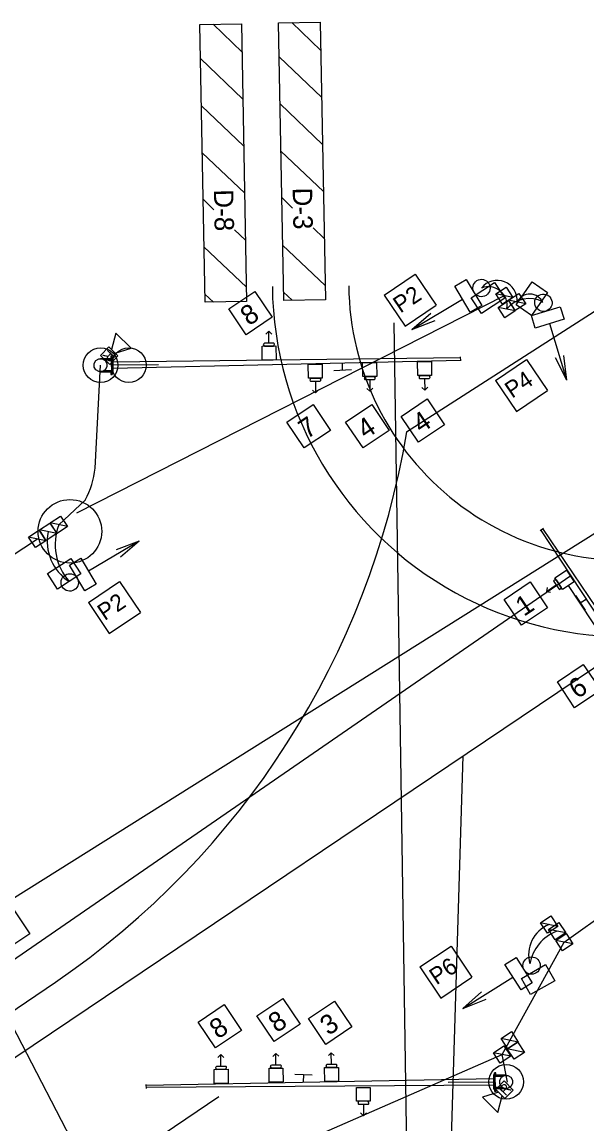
# Model space of a CAD drawing. Extents: x 509004 to 509991, y 882089 to 882397.
# Drawn here: x 509136.6 to 509218, y 882237.8 to 882396.5 of the extents above; entities that cross this region are included whole.
import ezdxf

# ---------------------------------------------------------------- set-up
doc = ezdxf.new("R2010")
doc.units = 0
for name, color, linetype in [('CLConst_dp', 7, 'Continuous'), ('ConstLines', 7, 'Continuous'), ('Default', 7, 'Continuous'), ('TextAlgnCardinalPnt', 7, 'Continuous'), ('TextAlgnCurveData', 7, 'Continuous'), ('TextAlgnStation100', 7, 'Continuous'), ('TextAlgnStation1000', 7, 'Continuous'), ('TextAlgnStation500', 7, 'Continuous'), ('TextAlgnTangent', 7, 'Continuous'), ('TextAlgnTicks1000', 7, 'Continuous'), ('TextAlgnTicks500', 7, 'Continuous'), ('TextAlgnTicks5000', 7, 'Continuous')]:
    doc.layers.add(name, color=color, linetype=linetype)

msp = doc.modelspace()

# ---------------------------------------------------------------- linework, layer by layer
at = {"layer": 'CLConst_dp'}
for p, q in [((509147.93, 882348.06), (509149.41, 882348.08)), ((509147.93, 882348.06), (509147.93, 882348)), ((509149.4, 882348.43), (509149.41, 882347.87)), ((509149.4, 882348.43), (509149.57, 882348.43)), ((509149.57, 882348.43), (509149.6, 882345.76)), ((509149.57, 882348.14), (509149.74, 882348.14)), ((509149.61, 882346.06), (509149.57, 882348.14)), ((509149.77, 882346.06), (509149.74, 882348.14)), ((509149.75, 882347.56), (509199.74, 882348.17)), ((509199.74, 882348.29), (509199.75, 882347.71)), ((509147.93, 882348), (509149.41, 882348.01)), ((509148.42, 882347.86), (509149.49, 882347.87)), ((509149.49, 882347.87), (509149.51, 882346.32)), ((509149.76, 882346.64), (509199.75, 882347.83)), ((509147.95, 882346.16), (509149.43, 882346.18)), ((509147.95, 882346.1), (509147.95, 882346.16)), ((509147.95, 882346.1), (509149.43, 882346.11)), ((509148.44, 882346.31), (509149.51, 882346.32)), ((509149.43, 882346.32), (509149.43, 882345.76)), ((509149.43, 882345.76), (509149.6, 882345.76)), ((509149.61, 882346.06), (509149.77, 882346.06)), ((509211.24, 882323.28), (509211.73, 882323.61)), ((509238.84, 882281.59), (509211.35, 882323.35)), ((509239.6, 882282.09), (509211.62, 882323.54)), ((509204.68, 882244.87), (509204.52, 882244.86)), ((509204.52, 882244.86), (509204.54, 882242.78)), ((509204.85, 882245.16), (509204.68, 882245.16)), ((509204.71, 882242.49), (509204.68, 882245.16)), ((509204.68, 882244.87), (509204.71, 882242.78)), ((509204.86, 882244.6), (509204.85, 882245.16)), ((509204.52, 882244.28), (509154.53, 882243.35)), ((509154.54, 882242.9), (509154.53, 882243.48)), ((509204.54, 882243.36), (509154.54, 882243.02)), ((509205.85, 882244.62), (509204.78, 882244.6)), ((509204.8, 882243.05), (509204.78, 882244.6)), ((509206.34, 882244.83), (509204.85, 882244.81)), ((509206.34, 882244.76), (509204.86, 882244.75)), ((509206.34, 882244.83), (509206.34, 882244.76)), ((509204.71, 882242.78), (509204.54, 882242.78)), ((509204.88, 882242.49), (509204.71, 882242.49)), ((509205.87, 882243.06), (509204.8, 882243.05)), ((509204.88, 882242.49), (509204.88, 882243.05)), ((509206.36, 882242.93), (509204.88, 882242.91)), ((509206.36, 882242.86), (509204.88, 882242.85)), ((509206.36, 882242.86), (509206.36, 882242.93))]:
    msp.add_line(p, q, dxfattribs=at)
for points in [[(509148.85, 882347.34), (509148.86, 882346.84), (509148.62, 882346.41), (509148.19, 882346.16), (509147.7, 882346.16), (509147.27, 882346.4), (509147.02, 882346.82), (509147.02, 882347.32), (509147.26, 882347.75), (509147.68, 882348), (509148.17, 882348), (509148.6, 882347.76)], [(509205.43, 882243.59), (509205.43, 882244.08), (509205.67, 882244.51), (509206.09, 882244.76), (509206.58, 882244.77), (509207.01, 882244.53), (509207.26, 882244.1), (509207.27, 882243.61), (509207.03, 882243.18), (509206.61, 882242.93), (509206.11, 882242.92), (509205.68, 882243.16)]]:
    msp.add_lwpolyline(points, close=True, dxfattribs=at)
for centre in [(509147.95, 882347.08), (509206.33, 882243.85)]:
    msp.add_circle(centre, 2.5, dxfattribs=at)
at = {"layer": 'ConstLines'}
for p, q in [((509224.06, 882358.02), (509191.98, 882337.43)), ((509192.24, 882220.42), (509190.2, 882353.18)), ((509238.53, 882335.06), (509130.35, 882267.1)), ((509114.28, 882246.89), (509215.66, 882316.8)), ((509220.55, 882307.45), (509215.3, 882315.34)), ((509216.99, 882312.83), (509217.89, 882313.44)), ((509121.5, 882237.9), (509226.04, 882308.24)), ((509198.03, 882220.51), (509200.14, 882290.82)), ((509118.93, 882242.94), (509141.44, 882258.22))]:
    msp.add_line(p, q, dxfattribs=at)
for centre, radius in [((509152.01, 882347.1), 2.5), ((509143.53, 882323.15), 4.58)]:
    msp.add_circle(centre, radius, dxfattribs=at)
for centre, radius, start, end in [((509223.67, 882358.96), 51, 180.6251, 301.6373), ((509223.67, 882358.96), 40, 180.6251, 283.6453), ((509073.68, 882357.25), 120, 304.3833, 350.5102)]:
    msp.add_arc(centre, radius, start, end, dxfattribs=at)
at = {"layer": 'Default'}
msp.add_line((509133.54, 882220.5), (509164.96, 882241.77), dxfattribs=at)
at = {"layer": 'TextAlgnCardinalPnt'}
for p, q in [((509150.12, 882223.33), (509108.95, 882302.45)), ((509205.76, 882247.8), (509214.71, 882263.99)), ((509150.34, 882223.59), (509205.76, 882247.8))]:
    msp.add_line(p, q, dxfattribs=at)
msp.add_lwpolyline([(509144.53, 882325.81), (509206.08, 882357.1), (509206.08, 882357.1)], dxfattribs=at)
at = {"layer": 'TextAlgnCurveData'}
for p, q in [((509147.15, 882332.26), (509147.95, 882347.08)), ((509141.93, 882324.1), (509145.75, 882327.67)), ((509110.42, 882303.44), (509138.84, 882322.08)), ((509214.71, 882263.99), (509224.45, 882270.93)), ((509206.51, 882243.8), (509205.76, 882247.8))]:
    msp.add_line(p, q, dxfattribs=at)
for centre, radius, start, end in [((509205.05, 882356.42), 2.88, 355.3581, 141.8161), ((509203.78, 882355.7), 2.69, 348.1569, 111.8269), ((509209.66, 882352.49), 4.2, 61.8296, 140.6841), ((509209.75, 882355.27), 2.05, 23.7943, 153.5559), ((509134.81, 882333.51), 12.4, 331.8713, 354.1881), ((509147.16, 882321.73), 6.91, 168.5924, 237.201), ((509149.48, 882321.25), 8.07, 159.3314, 221.3772), ((509214.29, 882262.13), 4.72, 111.9295, 195.9285), ((509215.75, 882259.86), 6.07, 109.9634, 170.7714)]:
    msp.add_arc(centre, radius, start, end, dxfattribs=at)
at = {"layer": 'TextAlgnStation100'}
for p, q in [((509204.84, 882357.35), (509206.34, 882358.34)), ((509206.34, 882358.34), (509207.32, 882356.84)), ((509205.82, 882355.86), (509204.84, 882357.35)), ((509207.32, 882356.84), (509204.84, 882357.35)), ((509205.17, 882355.41), (509206.67, 882356.39)), ((509207.32, 882356.84), (509205.82, 882355.86)), ((509206.67, 882356.44), (509208.17, 882357.43)), ((509207.66, 882354.95), (509206.67, 882356.44)), ((509209.15, 882355.93), (509206.67, 882356.44)), ((509206.67, 882356.39), (509207.66, 882354.89)), ((509208.17, 882357.43), (509209.15, 882355.93)), ((509206.16, 882353.91), (509205.17, 882355.41)), ((509207.66, 882354.89), (509205.17, 882355.41)), ((509207.66, 882354.89), (509206.16, 882353.91)), ((509209.15, 882355.93), (509207.66, 882354.95)), ((509139.15, 882323.35), (509140.65, 882324.34)), ((509140.65, 882324.34), (509141.63, 882322.84)), ((509140.68, 882324.36), (509142.18, 882325.34)), ((509141.67, 882322.86), (509140.68, 882324.36)), ((509143.17, 882323.84), (509140.68, 882324.36)), ((509142.18, 882325.34), (509143.17, 882323.84)), ((509137.57, 882322.32), (509139.07, 882323.3)), ((509139.07, 882323.3), (509140.06, 882321.8)), ((509140.13, 882321.85), (509139.15, 882323.35)), ((509141.63, 882322.84), (509139.15, 882323.35)), ((509141.63, 882322.84), (509140.13, 882321.85)), ((509143.17, 882323.84), (509141.67, 882322.86)), ((509138.56, 882320.82), (509137.57, 882322.32)), ((509140.06, 882321.8), (509137.57, 882322.32)), ((509140.06, 882321.8), (509138.56, 882320.82)), ((509211.29, 882266.77), (509212.79, 882267.75)), ((509212.79, 882267.75), (509213.77, 882266.25)), ((509212.27, 882265.27), (509211.29, 882266.77)), ((509213.77, 882266.25), (509211.29, 882266.77)), ((509213.77, 882266.25), (509212.27, 882265.27)), ((509212.43, 882265.82), (509213.93, 882266.81)), ((509213.41, 882264.33), (509212.43, 882265.82)), ((509214.91, 882265.31), (509212.43, 882265.82)), ((509213.93, 882266.81), (509214.91, 882265.31)), ((509214.91, 882265.31), (509213.41, 882264.33)), ((509213.47, 882264.24), (509214.97, 882265.23)), ((509214.45, 882262.75), (509213.47, 882264.24)), ((509215.95, 882263.73), (509213.47, 882264.24)), ((509214.97, 882265.23), (509215.95, 882263.73)), ((509215.95, 882263.73), (509214.45, 882262.75)), ((509205.61, 882250.1), (509207.11, 882251.09)), ((509206.59, 882248.61), (509205.61, 882250.1)), ((509208.09, 882249.59), (509205.61, 882250.1)), ((509207.11, 882251.09), (509208.09, 882249.59)), ((509204.52, 882248.06), (509206.02, 882249.04)), ((509205.5, 882246.56), (509204.52, 882248.06)), ((509207, 882247.54), (509204.52, 882248.06)), ((509206.02, 882249.04), (509207, 882247.54)), ((509206.49, 882248.61), (509207.99, 882249.6)), ((509207.47, 882247.12), (509206.49, 882248.61)), ((509208.97, 882248.1), (509206.49, 882248.61)), ((509208.09, 882249.59), (509206.59, 882248.61)), ((509208.97, 882248.1), (509207.47, 882247.12)), ((509207.99, 882249.6), (509208.97, 882248.1)), ((509207, 882247.54), (509205.5, 882246.56))]:
    msp.add_line(p, q, dxfattribs=at)
at = {"layer": 'TextAlgnStation1000'}
for p, q in [((509171.75, 882351.54), (509172.16, 882351.97)), ((509172.19, 882350.25), (509172.16, 882351.97)), ((509172.6, 882351.55), (509172.16, 882351.97)), ((509172.85, 882350.26), (509171.53, 882350.24)), ((509172.85, 882350.26), (509171.53, 882350.24)), ((509172.85, 882349.84), (509171.54, 882349.82)), ((509178.21, 882345.21), (509179.52, 882345.23)), ((509186.04, 882345.44), (509187.35, 882345.46)), ((509186.05, 882345.02), (509187.36, 882345.04)), ((509186.05, 882345.02), (509187.36, 882345.04)), ((509186.71, 882345.03), (509186.73, 882343.32)), ((509193.94, 882345.59), (509195.25, 882345.61)), ((509193.95, 882345.17), (509195.26, 882345.19)), ((509193.95, 882345.17), (509195.26, 882345.19)), ((509194.6, 882345.18), (509194.63, 882343.47)), ((509178.22, 882344.78), (509179.53, 882344.8)), ((509178.22, 882344.78), (509179.53, 882344.8)), ((509178.47, 882343.5), (509178.9, 882343.08)), ((509178.88, 882344.79), (509178.9, 882343.08)), ((509179.32, 882343.51), (509178.9, 882343.08)), ((509186.3, 882343.74), (509186.73, 882343.32)), ((509187.15, 882343.75), (509186.73, 882343.32)), ((509194.2, 882343.89), (509194.63, 882343.47)), ((509195.05, 882343.9), (509194.63, 882343.47)), ((509213.56, 882315.4), (509212.13, 882314.46)), ((509212.25, 882315.05), (509212.13, 882314.46)), ((509213.2, 882315.95), (509213.92, 882314.85)), ((509213.2, 882315.95), (509213.92, 882314.85)), ((509213.56, 882316.18), (509214.27, 882315.08)), ((509212.72, 882314.34), (509212.13, 882314.46)), ((509180.74, 882247.63), (509181.16, 882248.06)), ((509181.19, 882246.35), (509181.16, 882248.06)), ((509181.59, 882247.64), (509181.16, 882248.06)), ((509164.84, 882247.35), (509165.26, 882247.78)), ((509165.28, 882246.07), (509165.26, 882247.78)), ((509165.69, 882247.36), (509165.26, 882247.78)), ((509172.74, 882247.53), (509173.16, 882247.96)), ((509173.19, 882246.25), (509173.16, 882247.96)), ((509173.59, 882247.54), (509173.16, 882247.96)), ((509165.94, 882246.08), (509164.63, 882246.06)), ((509165.94, 882246.08), (509164.63, 882246.06)), ((509165.95, 882245.66), (509164.64, 882245.64)), ((509173.84, 882246.26), (509172.53, 882246.24)), ((509173.84, 882246.26), (509172.53, 882246.24)), ((509173.85, 882245.84), (509172.54, 882245.82)), ((509181.84, 882246.36), (509180.53, 882246.34)), ((509181.84, 882246.36), (509180.53, 882246.34)), ((509181.85, 882245.94), (509180.54, 882245.92)), ((509185.15, 882240.64), (509186.44, 882240.64)), ((509185.8, 882240.64), (509185.8, 882238.95)), ((509185.38, 882239.37), (509185.8, 882238.95)), ((509186.21, 882239.37), (509185.8, 882238.95))]:
    msp.add_line(p, q, dxfattribs=at)
for points in [[(509172.67, 882353.99), (509168.92, 882351.47), (509166.42, 882355.19), (509170.17, 882357.71)], [(509171.2, 882349.82), (509173.2, 882349.85), (509173.23, 882347.85), (509171.23, 882347.82)], [(509179.87, 882345.23), (509177.87, 882345.2), (509177.84, 882347.2), (509179.84, 882347.23)], [(509187.7, 882345.47), (509185.7, 882345.44), (509185.67, 882347.44), (509187.67, 882347.47)], [(509195.6, 882345.62), (509193.6, 882345.59), (509193.57, 882347.59), (509195.57, 882347.62)], [(509197.46, 882338.51), (509193.71, 882335.99), (509191.21, 882339.71), (509194.96, 882342.23)], [(509181.03, 882337.7), (509177.28, 882335.18), (509174.78, 882338.9), (509178.53, 882341.42)], [(509189.48, 882337.69), (509185.73, 882335.17), (509183.23, 882338.88), (509186.98, 882341.4)], [(509214.46, 882314.79), (509213.37, 882316.47), (509215.04, 882317.56), (509216.14, 882315.89)], [(509212.27, 882312.14), (509208.53, 882309.62), (509206.03, 882313.34), (509209.78, 882315.86)], [(509219.95, 882300.26), (509216.2, 882297.74), (509213.71, 882301.46), (509217.45, 882303.98)], [(509137.74, 882265.2), (509133.99, 882262.68), (509131.49, 882266.4), (509135.24, 882268.92)], [(509168.22, 882251.26), (509164.47, 882248.74), (509161.97, 882252.46), (509165.72, 882254.98)], [(509176.68, 882252.17), (509172.93, 882249.65), (509170.43, 882253.36), (509174.18, 882255.88)], [(509184.13, 882251.78), (509180.38, 882249.26), (509177.89, 882252.97), (509181.63, 882255.49)], [(509164.29, 882245.63), (509166.29, 882245.66), (509166.32, 882243.66), (509164.32, 882243.63)], [(509172.2, 882245.81), (509174.19, 882245.84), (509174.23, 882243.84), (509172.23, 882243.81)], [(509180.19, 882245.91), (509182.19, 882245.94), (509182.22, 882243.94), (509180.23, 882243.91)], [(509186.78, 882241.06), (509184.81, 882241.06), (509184.81, 882243.02), (509186.78, 882243.02)]]:
    msp.add_lwpolyline(points, close=True, dxfattribs=at)
for points in [[(509171.54, 882349.82), (509172.85, 882349.84)], [(509179.52, 882345.23), (509178.21, 882345.21)], [(509187.35, 882345.46), (509186.04, 882345.44)], [(509195.25, 882345.61), (509193.94, 882345.59)], [(509214.27, 882315.08), (509213.56, 882316.18)], [(509164.64, 882245.64), (509165.95, 882245.66)], [(509172.54, 882245.82), (509173.85, 882245.84)], [(509180.54, 882245.92), (509181.85, 882245.94)], [(509186.44, 882241.06), (509185.15, 882241.06)]]:
    msp.add_lwpolyline(points, dxfattribs=at)
for centre, radius, start, end in [((509171.54, 882350.11), 0.129, 90.8793, 210.1991), ((509171.54, 882350.11), 0.129, 90.8793, 210.1991), ((509169.35, 882348.84), 2.4, 24.0959, 30.1991), ((509169.35, 882348.84), 2.4, 24.0959, 30.1991), ((509172.85, 882350.13), 0.129, 331.5595, 90.8793), ((509172.85, 882350.13), 0.129, 331.5595, 90.8793), ((509175.07, 882348.93), 2.4, 151.5595, 157.6627), ((509175.07, 882348.93), 2.4, 151.5595, 157.6627), ((509178.22, 882344.91), 0.129, 151.5595, 270.8793), ((509178.22, 882344.91), 0.129, 151.5595, 270.8793), ((509176, 882346.12), 2.4, 331.5595, 337.6627), ((509176, 882346.12), 2.4, 331.5595, 337.6627), ((509181.71, 882346.2), 2.4, 204.0959, 210.1991), ((509181.71, 882346.2), 2.4, 204.0959, 210.1991), ((509179.53, 882344.93), 0.129, 270.8793, 30.1991), ((509179.53, 882344.93), 0.129, 270.8793, 30.1991), ((509186.05, 882345.15), 0.129, 151.5595, 270.8793), ((509186.05, 882345.15), 0.129, 151.5595, 270.8793), ((509183.83, 882346.36), 2.4, 331.5595, 337.6627), ((509183.83, 882346.36), 2.4, 331.5595, 337.6627), ((509189.54, 882346.44), 2.4, 204.0959, 210.1991), ((509189.54, 882346.44), 2.4, 204.0959, 210.1991), ((509187.36, 882345.17), 0.129, 270.8793, 30.1991), ((509187.36, 882345.17), 0.129, 270.8793, 30.1991), ((509193.94, 882345.3), 0.129, 151.5595, 270.8793), ((509193.94, 882345.3), 0.129, 151.5595, 270.8793), ((509191.72, 882346.51), 2.4, 331.5595, 337.6627), ((509191.72, 882346.51), 2.4, 331.5595, 337.6627), ((509197.44, 882346.59), 2.4, 204.0959, 210.1991), ((509197.44, 882346.59), 2.4, 204.0959, 210.1991), ((509195.26, 882345.32), 0.129, 270.8793, 30.1991), ((509195.26, 882345.32), 0.129, 270.8793, 30.1991), ((509213.31, 882316.02), 0.129, 93.9405, 213.2603), ((509213.31, 882316.02), 0.129, 93.9405, 213.2603), ((509213.14, 882318.54), 2.4, 273.9405, 280.0438), ((509213.14, 882318.54), 2.4, 273.9405, 280.0438), ((509214.03, 882314.92), 0.129, 213.2603, 332.5802), ((509214.03, 882314.92), 0.129, 213.2603, 332.5801), ((509216.27, 882313.76), 2.4, 146.4769, 152.5802), ((509216.27, 882313.76), 2.4, 146.4769, 152.5802), ((509164.63, 882245.93), 0.129, 90.8793, 210.1991), ((509164.63, 882245.93), 0.129, 90.8793, 210.1991), ((509162.45, 882244.66), 2.4, 24.0959, 30.1991), ((509162.45, 882244.66), 2.4, 24.0959, 30.1991), ((509165.94, 882245.95), 0.129, 331.5595, 90.8793), ((509165.94, 882245.95), 0.129, 331.5595, 90.8793), ((509168.16, 882244.74), 2.4, 151.5595, 157.6627), ((509168.16, 882244.74), 2.4, 151.5595, 157.6627), ((509172.53, 882246.11), 0.129, 90.8793, 210.1991), ((509172.53, 882246.11), 0.129, 90.8793, 210.1991), ((509170.35, 882244.84), 2.4, 24.0959, 30.1991), ((509170.35, 882244.84), 2.4, 24.0959, 30.1991), ((509173.85, 882246.13), 0.129, 331.5595, 90.8793), ((509173.85, 882246.13), 0.129, 331.5595, 90.8793), ((509176.07, 882244.92), 2.4, 151.5595, 157.6627), ((509176.07, 882244.92), 2.4, 151.5595, 157.6627), ((509180.53, 882246.21), 0.129, 90.8793, 210.1991), ((509180.53, 882246.21), 0.129, 90.8793, 210.1991), ((509178.35, 882244.94), 2.4, 24.0959, 30.1991), ((509178.35, 882244.94), 2.4, 24.0959, 30.1991), ((509181.85, 882246.23), 0.129, 331.5595, 90.8793), ((509181.85, 882246.23), 0.129, 331.5595, 90.8793), ((509184.07, 882245.02), 2.4, 151.5595, 157.6627), ((509184.07, 882245.02), 2.4, 151.5595, 157.6627), ((509185.15, 882240.77), 0.127, 150.6802, 270), ((509182.98, 882241.99), 2.36, 330.6802, 336.7834), ((509188.61, 882241.99), 2.36, 203.2166, 209.3198), ((509186.44, 882240.77), 0.127, 270, 29.3198)]:
    msp.add_arc(centre, radius, start, end, dxfattribs=at)
at = {"layer": 'TextAlgnStation500'}
for p, q in [((509188.76, 882357.19), (509193.24, 882360.2)), ((509193.24, 882360.2), (509196.25, 882355.72)), ((509188.76, 882357.19), (509191.78, 882352.71)), ((509192.77, 882352.24), (509200.07, 882356.58)), ((509191.78, 882352.71), (509196.25, 882355.72)), ((509192.77, 882352.24), (509195.48, 882354.57)), ((509192.77, 882352.24), (509196.12, 882353.5)), ((509215.08, 882344.92), (509212.61, 882353.06)), ((509215.08, 882344.92), (509213.46, 882348.12)), ((509215.08, 882344.92), (509214.65, 882348.48)), ((509204.8, 882344.89), (509209.28, 882347.9)), ((509209.28, 882347.9), (509212.29, 882343.42)), ((509204.8, 882344.89), (509207.81, 882340.41)), ((509207.81, 882340.41), (509212.29, 882343.42)), ((509153.52, 882321.75), (509146.21, 882317.4)), ((509153.52, 882321.75), (509150.17, 882320.48)), ((509153.52, 882321.75), (509150.81, 882319.41)), ((509146.18, 882312.91), (509150.66, 882315.92)), ((509150.66, 882315.92), (509153.68, 882311.44)), ((509146.18, 882312.91), (509149.2, 882308.43)), ((509149.2, 882308.43), (509153.68, 882311.44)), ((509193.92, 882260.4), (509198.4, 882263.41)), ((509198.4, 882263.41), (509201.41, 882258.93)), ((509193.92, 882260.4), (509196.94, 882255.92)), ((509196.94, 882255.92), (509201.41, 882258.93)), ((509200.12, 882254.42), (509207.32, 882258.94)), ((509200.12, 882254.42), (509202.78, 882256.82)), ((509200.12, 882254.42), (509203.44, 882255.77))]:
    msp.add_line(p, q, dxfattribs=at)
at = {"layer": 'TextAlgnTicks1000'}
for p, q in [((509162.24, 882396.15), (509168.24, 882396.26)), ((509162.98, 882356.16), (509162.24, 882396.15)), ((509168.32, 882392.19), (509164.13, 882396.19)), ((509168.24, 882396.26), (509168.97, 882356.27)), ((509173.58, 882396.4), (509179.58, 882396.51)), ((509174.31, 882356.41), (509173.58, 882396.4)), ((509179.65, 882392.43), (509175.46, 882396.44)), ((509179.58, 882396.51), (509180.31, 882356.52)), ((509168.44, 882385.41), (509162.33, 882391.24)), ((509179.78, 882385.66), (509173.67, 882391.49)), ((509179.9, 882378.88), (509173.79, 882384.71)), ((509168.57, 882378.63), (509162.46, 882384.46)), ((509168.69, 882371.85), (509162.58, 882377.69)), ((509180.02, 882372.1), (509173.92, 882377.93)), ((509164.24, 882369.47), (509162.7, 882370.98)), ((509175.58, 882369.72), (509174.04, 882371.22)), ((509167.23, 882366.6), (509168.81, 882365.08)), ((509178.56, 882366.85), (509180.15, 882365.32)), ((509162.83, 882364.14), (509168.94, 882358.3)), ((509174.16, 882364.39), (509180.27, 882358.55)), ((509174.29, 882357.58), (509175.51, 882356.43)), ((509162.95, 882357.33), (509164.18, 882356.18)), ((509168.97, 882356.27), (509162.98, 882356.16)), ((509180.31, 882356.52), (509174.31, 882356.41)), ((509149.51, 882349.35), (509150.06, 882348.81)), ((509205.78, 882241.82), (509205.23, 882242.37))]:
    msp.add_line(p, q, dxfattribs=at)
for points in [[(509150.06, 882348.81), (509152.36, 882349.53), (509150.16, 882351.72), (509149.51, 882349.35)], [(509205.23, 882242.37), (509202.94, 882241.65), (509205.14, 882239.46), (509205.78, 882241.82)]]:
    msp.add_lwpolyline(points, dxfattribs=at)
for points in [[(509150.45, 882348.42), (509149.27, 882347.19), (509147.95, 882348.5), (509149.13, 882349.74)], [(509204.85, 882242.76), (509206.03, 882243.99), (509207.35, 882242.68), (509206.17, 882241.44)]]:
    msp.add_lwpolyline(points, close=True, dxfattribs=at)
at = {"layer": 'TextAlgnTicks500'}
for p, q in [((509198.96, 882358.45), (509200.6, 882359.42)), ((509200.6, 882359.42), (509202.82, 882355.69)), ((509201.18, 882354.72), (509198.96, 882358.45)), ((509202.82, 882355.69), (509201.18, 882354.72)), ((509209.98, 882354.25), (509214.13, 882355.51)), ((509214.13, 882355.51), (509214.69, 882353.69)), ((509210.54, 882352.43), (509209.98, 882354.25)), ((509214.69, 882353.69), (509210.54, 882352.43)), ((509143.46, 882318.29), (509145.1, 882319.27)), ((509145.68, 882314.56), (509143.46, 882318.29)), ((509145.1, 882319.27), (509147.32, 882315.54)), ((509147.32, 882315.54), (509145.68, 882314.56)), ((509206.17, 882260.77), (509207.79, 882261.79)), ((509208.48, 882257.1), (509206.17, 882260.77)), ((509207.79, 882261.79), (509210.09, 882258.11)), ((509210.09, 882258.11), (509208.48, 882257.1))]:
    msp.add_line(p, q, dxfattribs=at)
for points in [[(509206.13, 882356.74), (509202.78, 882354.55), (509201.32, 882356.79), (509204.67, 882358.97)], [(509207.8, 882355.79), (509210.09, 882359.07), (509212.28, 882357.54), (509209.98, 882354.26)], [(509140.29, 882317.06), (509143.64, 882319.24), (509145.1, 882317.01), (509141.75, 882314.83)], [(509208.53, 882258.75), (509212, 882260.74), (509213.33, 882258.43), (509209.86, 882256.44)]]:
    msp.add_lwpolyline(points, close=True, dxfattribs=at)
for centre, major_axis in [((509202.79, 882358.2), (0.86, -0.908)), ((509211.7, 882356.08), (1.09, 0.62)), ((509143.5, 882315.79), (-0.86, 0.908)), ((509210, 882260.61), (0.881, -0.887))]:
    msp.add_ellipse(centre, major_axis=major_axis, ratio=0.999996, dxfattribs=at)
at = {"layer": 'TextAlgnTicks5000'}
for p, q in [((509156.26, 882347.15), (509149.76, 882347.09)), ((509181.55, 882346.34), (509184.05, 882346.44)), ((509182.8, 882346.39), (509182.76, 882347.41)), ((509216.33, 882313.89), (509217.7, 882311.8)), ((509217.01, 882312.84), (509217.86, 882313.4)), ((509178.41, 882244.81), (509175.91, 882244.91)), ((509177.16, 882244.86), (509177.12, 882243.84)), ((509204.49, 882243.82), (509197.99, 882243.76))]:
    msp.add_line(p, q, dxfattribs=at)

# ---------------------------------------------------------------- texts
at = {"layer": 'TextAlgnStation1000'}
for s, p in [('8', (509169.29, 882352.67)), ('4', (509194.08, 882337.19)), ('7', (509177.65, 882336.38)), ('4', (509186.1, 882336.36)), ('1', (509208.9, 882310.82)), ('6', (509216.57, 882298.94)), ('8', (509164.84, 882249.94)), ('8', (509173.3, 882250.84)), ('3', (509180.75, 882250.45))]:
    msp.add_text(s, height=2.8, rotation=33.9138, dxfattribs=at).set_placement(p)
at = {"layer": 'TextAlgnStation500'}
for s, p in [('P2', (509191.11, 882354.5)), ('P4', (509207.19, 882342.23)), ('P2', (509148.53, 882310.22)), ('P6', (509196.31, 882257.74))]:
    msp.add_text(s, height=2.399, rotation=33.9138, dxfattribs=at).set_placement(p)
at = {"layer": 'TextAlgnTangent'}
for s, p in [('D-8', (509164.26, 882372.39)), ('D-3', (509175.6, 882372.64))]:
    msp.add_text(s, height=2.8, rotation=271.0474, dxfattribs=at).set_placement(p)
at = {"layer": 'TextAlgnTicks1000'}
for rotation, p in [(226.3004, (509149.08, 882349.42)), (46.3004, (509206.22, 882241.76))]:
    msp.add_text('R', height=1.49, rotation=rotation, dxfattribs=at).set_placement(p)

doc.saveas('drawing.dxf')
